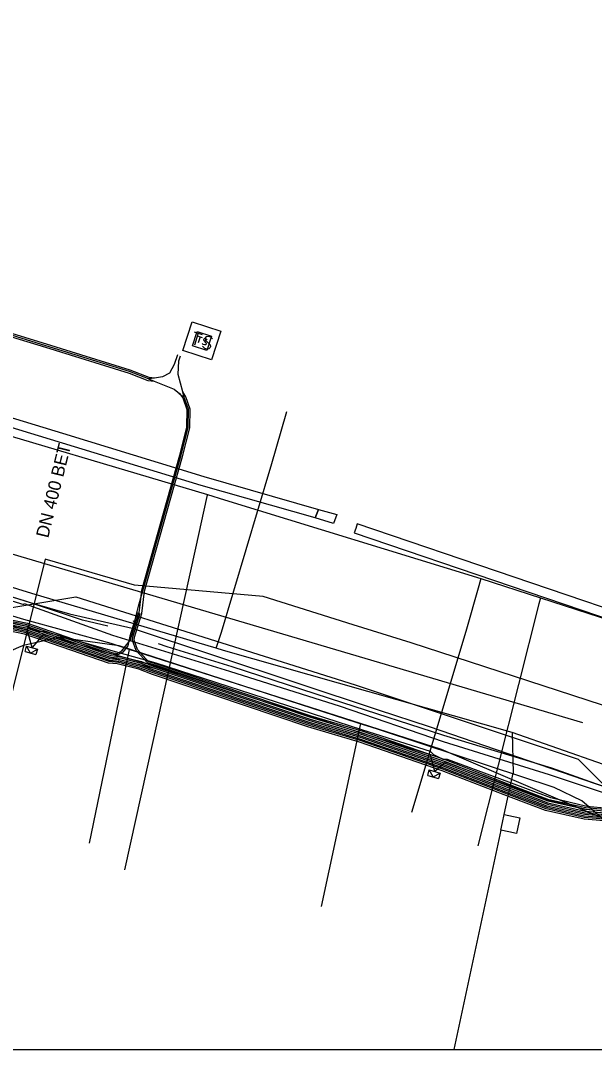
# Model space of a CAD drawing. Extents: x -599951 to -598963, y -1164095 to -1162939.
# Drawn here: x -599602.6 to -599566.7, y -1164094.7 to -1164030.3 of the extents above; entities that cross this region are included whole.
import ezdxf

# ---------------------------------------------------------------- set-up
doc = ezdxf.new("R2010")
doc.units = 0
for name, color, linetype in [('25', 7, 'Continuous'), ('31', 7, 'Continuous'), ('Level 3', 7, 'Continuous'), ('Vrstva 1', 7, 'Continuous'), ('Vrstva 12', 7, 'Continuous'), ('Vrstva 13', 7, 'Continuous'), ('Vrstva 16', 7, 'Continuous'), ('Vrstva 19', 7, 'Continuous'), ('Vrstva 3', 7, 'Continuous'), ('Vrstva 4', 7, 'Continuous'), ('Vrstva 42', 7, 'Continuous'), ('Vrstva 43', 7, 'Continuous'), ('Vrstva 44', 7, 'Continuous'), ('Vrstva 45', 7, 'Continuous'), ('Vrstva 53', 7, 'Continuous'), ('Vrstva 55', 7, 'Continuous'), ('Vrstva 58', 7, 'Continuous')]:
    doc.layers.add(name, color=color, linetype=linetype)

# ---------------------------------------------------------------- blocks, each defined once
blk = doc.blocks.new('VN640')
at = {"layer": '25'}
for points in [[(-1.89, 1.889), (1.889, 1.889)], [(-1.89, -1.89), (-1.89, 1.889)], [(-1.26, 0.787), (-0.221, 0.787)], [(-0.725, 0.787), (-0.725, -0.788)], [(1.197, 0.661), (0.945, 0.787), (0.661, 0.787), (0.409, 0.661), (0.283, 0.472), (0.283, 0.409), (0.409, 0.22), (1.133, -0.158), (1.259, -0.316), (1.259, -0.473), (1.133, -0.662), (0.913, -0.788), (0.629, -0.788), (0.503, -0.725), (0.283, -0.599)], [(1.889, 1.889), (1.889, -1.89)], [(1.889, -1.89), (-1.89, -1.89)]]:
    blk.add_lwpolyline(points, dxfattribs=at)
blk = doc.blocks.new('NN640')
at = {"layer": '25'}
for points in [[(-1.89, 1.889), (1.889, 1.889)], [(-1.89, -1.89), (-1.89, 1.889)], [(1.889, 1.889), (1.889, -1.89)], [(-1.26, 0.787), (-0.221, 0.787)], [(-0.725, 0.787), (-0.725, -0.788)], [(1.197, 0.661), (0.945, 0.787), (0.661, 0.787), (0.409, 0.661), (0.283, 0.472), (0.283, 0.409), (0.409, 0.22), (1.133, -0.158), (1.259, -0.316), (1.259, -0.473), (1.133, -0.662), (0.913, -0.788), (0.629, -0.788), (0.503, -0.725), (0.283, -0.599)], [(1.889, -1.89), (-1.89, -1.89)]]:
    blk.add_lwpolyline(points, dxfattribs=at)
blk = doc.blocks.new('NN630')
at = {"layer": '31'}
for points in [[(-0.003, -0.7), (-0.703, 0)], [(-0.703, -0.7), (-0.703, 0), (0.697, 0), (0.697, -0.7)], [(-0.003, -0.7), (0.697, 0)], [(-0.703, -0.7), (0.697, -0.7)]]:
    blk.add_lwpolyline(points, dxfattribs=at)

msp = doc.modelspace()

# ---------------------------------------------------------------- linework, layer by layer
at = {"layer": 'Level 3'}
msp.add_lwpolyline([(-599670.761, -1164034.874), (-599635.968, -1164045.241), (-599626.064, -1164047.883), (-599617.019, -1164050.914), (-599600, -1164056.104), (-599591.155, -1164058.802), (-599583.98, -1164060.87), (-599584.17, -1164061.41), (-599591.325, -1164059.378), (-599600, -1164056.732), (-599617.201, -1164051.486), (-599626.236, -1164048.457), (-599636.132, -1164045.819), (-599670.939, -1164035.446)], dxfattribs=at)
msp.add_lwpolyline([(-599584.17, -1164061.41), (-599583.98, -1164060.87), (-599582.83, -1164061.2), (-599583.03, -1164061.76)], close=True, dxfattribs=at)
at = {"layer": 'Vrstva 1'}
msp.add_line((-599567.415, -1164074.246), (-599604.11, -1164063.39), dxfattribs=at)
at = {"layer": 'Vrstva 12'}
msp.add_line((-599581.54, -1164074.23), (-599596.47, -1164069.41), dxfattribs=at)
for points in [[(-599613.46, -1164062.85), (-599613.16, -1164063.2), (-599611.72, -1164063.65), (-599602.03, -1164066.71), (-599599.57, -1164067.42), (-599595.65, -1164068.31), (-599580.24, -1164073.43), (-599577.04, -1164074.47), (-599566.64, -1164078.04), (-599562.59, -1164079.3), (-599551.43, -1164082.77), (-599546.18, -1164085.05), (-599534.35, -1164089.62), (-599520.153, -1164094.695)], [(-599512.817, -1164094.695), (-599549.011, -1164079.426), (-599551.753, -1164080.567), (-599560.66, -1164074.929), (-599578.175, -1164069.238), (-599581.79, -1164068.099), (-599587.439, -1164066.331), (-599595.493, -1164065.607), (-599599.144, -1164064.549), (-599601.105, -1164063.983), (-599607.16, -1164088.185), (-599608.496, -1164094.695)], [(-599596.47, -1164069.41), (-599600.24, -1164068.89), (-599602.46, -1164069.4), (-599602.72, -1164069.51), (-599603.14, -1164069.68), (-599603.87, -1164071.93)], [(-599565.95, -1164080.45), (-599567.47, -1164079.13), (-599569.21, -1164078.29), (-599577.43, -1164075.58), (-599580.28, -1164074.63), (-599581.54, -1164074.23)]]:
    msp.add_lwpolyline(points, dxfattribs=at)
at = {"layer": 'Vrstva 13'}
for points in [[(-599607.67, -1164054.96), (-599590.92, -1164059.94), (-599589.853, -1164060.27), (-599573.8, -1164065.2), (-599570.07, -1164066.42), (-599549.24, -1164073.15), (-599540.472, -1164075.88), (-599508.435, -1164089.969), (-599502.44, -1164092.61), (-599497.429, -1164094.695)], [(-599590.92, -1164059.94), (-599590.96, -1164060.07), (-599591.68, -1164063.31), (-599596.119, -1164083.448)], [(-599573.8, -1164065.2), (-599573.93, -1164065.66), (-599574.75, -1164068.52), (-599578.146, -1164079.846)], [(-599570.07, -1164066.42), (-599570.16, -1164066.78), (-599573.98, -1164081.94)]]:
    msp.add_lwpolyline(points, dxfattribs=at)
at = {"layer": 'Vrstva 16'}
for points in [[(-599532.23, -1164094.695), (-599576.26, -1164075.92), (-599581.33, -1164074.29), (-599595.84, -1164069.64), (-599596.96, -1164069.28), (-599602.44, -1164067.76), (-599618.73, -1164062.85), (-599666.38, -1164048.5), (-599672.28, -1164046.86), (-599687.99, -1164042.5)], [(-599595.84, -1164069.64), (-599598.33, -1164081.77)], [(-599581.33, -1164074.29), (-599583.8, -1164085.75)]]:
    msp.add_lwpolyline(points, dxfattribs=at)
at = {"layer": 'Vrstva 19'}
for points in [[(-599517.408, -1164094.695), (-599537.5, -1164086.87), (-599571.84, -1164074.84), (-599589.93, -1164069.71), (-599590.38, -1164069.57), (-599590.89, -1164069.41), (-599601.93, -1164066.13), (-599608.97, -1164063.96), (-599646.01, -1164052.54), (-599646.71, -1164052.33), (-599646.97, -1164052.25), (-599649.244, -1164051.504), (-599665.68, -1164046.42), (-599687.59, -1164039.86)], [(-599590.38, -1164069.57), (-599590.19, -1164068.99), (-599590.05, -1164068.56), (-599586.96, -1164058.21), (-599586.94, -1164058.14), (-599585.95, -1164054.74)], [(-599571.84, -1164074.84), (-599571.77, -1164077.39)], [(-599572.44, -1164080.48), (-599572.33, -1164079.99), (-599571.77, -1164077.39)], [(-599572.33, -1164079.99), (-599572.04, -1164080.05), (-599571.35, -1164080.2), (-599571.56, -1164081.18), (-599572.05, -1164081.07), (-599572.54, -1164080.97), (-599575.487, -1164094.695)], [(-599572.54, -1164080.97), (-599572.44, -1164080.48)]]:
    msp.add_lwpolyline(points, dxfattribs=at)
at = {"layer": 'Vrstva 3'}
msp.add_lwpolyline([(-599492.33, -1164094.695), (-599491.183, -1164094.695), (-599491.12, -1164094.53), (-599497.905, -1164092.099), (-599500, -1164091.28), (-599520.117, -1164083.412), (-599528.111, -1164080.071), (-599548.984, -1164072.466), (-599561.867, -1164068.455), (-599581.544, -1164061.776), (-599581.64, -1164062.06), (-599581.735, -1164062.342), (-599562.053, -1164069.025), (-599549.176, -1164073.034), (-599528.329, -1164080.629), (-599520.343, -1164083.968), (-599500, -1164091.924), (-599498.115, -1164092.661)], close=True, dxfattribs=at)
at = {"layer": 'Vrstva 42'}
for points in [[(-599565.43, -1164079.839), (-599567.196, -1164079.669), (-599569.479, -1164079.126), (-599572.125, -1164078.144), (-599576.007, -1164076.713), (-599576.69, -1164077.29), (-599576.872, -1164076.585), (-599576.961, -1164076.241), (-599581.25, -1164074.885), (-599584.411, -1164073.875), (-599594.199, -1164070.686), (-599597.037, -1164069.906), (-599601.23, -1164068.704), (-599601.92, -1164069.53), (-599602.229, -1164068.421), (-599611.444, -1164066.257), (-599613.443, -1164065.737), (-599616.851, -1164065.018), (-599617.63, -1164065.53)], [(-599565.41, -1164079.64), (-599567.164, -1164079.471), (-599569.421, -1164078.934), (-599572.055, -1164077.956), (-599575.885, -1164076.546), (-599576.152, -1164076.53), (-599576.753, -1164076.243), (-599576.96, -1164076.035), (-599581.19, -1164074.695), (-599584.349, -1164073.685), (-599594.141, -1164070.494), (-599596.983, -1164069.714), (-599601.132, -1164068.524), (-599601.444, -1164068.54), (-599601.897, -1164068.412), (-599602.237, -1164068.213), (-599611.396, -1164066.063)]]:
    msp.add_lwpolyline(points, dxfattribs=at)
at = {"layer": 'Vrstva 44'}
for p, q in [((-599601.05, -1164050.62), (-599606.97, -1164048.81)), ((-599595.81, -1164052.24), (-599601.05, -1164050.62)), ((-599594.62, -1164052.7), (-599595.81, -1164052.24)), ((-599594.247, -1164052.645), (-599594.62, -1164052.7)), ((-599594.62, -1164052.7), (-599594.274, -1164052.838)), ((-599592.38, -1164053.86), (-599592.473, -1164053.51)), ((-599592.717, -1164053.586), (-599592.38, -1164053.86)), ((-599592.11, -1164054.6), (-599592.38, -1164053.86)), ((-599592.14, -1164055.74), (-599592.11, -1164054.6)), ((-599592.59, -1164057.53), (-599592.14, -1164055.74)), ((-599595.24, -1164066.94), (-599592.59, -1164057.53)), ((-599595.48, -1164067.85), (-599595.24, -1164066.94)), ((-599595.48, -1164067.85), (-599595.594, -1164067.891)), ((-599595.432, -1164068.06), (-599595.48, -1164067.85))]:
    msp.add_line(p, q, dxfattribs=at)
for points in [[(-599592.804, -1164051.197), (-599593.016, -1164051.8), (-599593.3, -1164052.33), (-599593.74, -1164052.57), (-599594.247, -1164052.645), (-599594.584, -1164052.607), (-599595.777, -1164052.146), (-599601.021, -1164050.524), (-599606.942, -1164048.714), (-599614.66, -1164046.524), (-599624.688, -1164043.135), (-599633.419, -1164040.135), (-599640.341, -1164037.974), (-599642.239, -1164037.405), (-599644.228, -1164036.705), (-599647.942, -1164035.504), (-599650.972, -1164034.727), (-599651.601, -1164034.365), (-599651.846, -1164034.01), (-599652.008, -1164033.22), (-599651.724, -1164031.781)], [(-599713.076, -1164035.902), (-599703.955, -1164038.752), (-599695.016, -1164041.252), (-599688.692, -1164043.173), (-599677.704, -1164046.543), (-599672.728, -1164047.994), (-599667.14, -1164049.944), (-599657.488, -1164052.642), (-599649.966, -1164054.832), (-599642.274, -1164057.053), (-599633.284, -1164059.853), (-599627.565, -1164061.482), (-599619.491, -1164063.974), (-599613.646, -1164065.724), (-599612.857, -1164065.953), (-599611.723, -1164066.031), (-599602.21, -1164068), (-599596.912, -1164069.837), (-599596.588, -1164069.897), (-599596.29, -1164069.74), (-599595.75, -1164069.044), (-599595.695, -1164068.82), (-599595.236, -1164067.34)], [(-599606.998, -1164048.906), (-599601.079, -1164050.716), (-599595.843, -1164052.335), (-599594.656, -1164052.793), (-599594.274, -1164052.838), (-599593.02, -1164053.34), (-599592.676, -1164053.62), (-599592.474, -1164053.894), (-599592.21, -1164054.616), (-599592.24, -1164055.726), (-599592.687, -1164057.504), (-599595.064, -1164065.946), (-599595.236, -1164067.34)], [(-599595.044, -1164067.4), (-599594.871, -1164065.998), (-599592.493, -1164057.556), (-599592.04, -1164055.754), (-599592.01, -1164054.584), (-599592.286, -1164053.826), (-599592.473, -1164053.51), (-599592.76, -1164052.43), (-599592.724, -1164051.573), (-599592.616, -1164051.263)], [(-599657.543, -1164052.834), (-599650.022, -1164055.024), (-599642.331, -1164057.244), (-599633.341, -1164060.044), (-599627.622, -1164061.674), (-599619.551, -1164064.164), (-599613.642, -1164065.934), (-599612.892, -1164066.151), (-599611.736, -1164066.231), (-599602.263, -1164068.193), (-599596.981, -1164070.024), (-599596.262, -1164070.1), (-599595.065, -1164070.401), (-599594.222, -1164070.724), (-599584.49, -1164074.005), (-599581.239, -1164074.975), (-599576.046, -1164076.776), (-599572.154, -1164078.277), (-599569.601, -1164079.244), (-599567.255, -1164079.771), (-599563.761, -1164080.071)], [(-599657.597, -1164053.026), (-599650.078, -1164055.216), (-599642.389, -1164057.436), (-599633.399, -1164060.236), (-599627.678, -1164061.866), (-599619.609, -1164064.356), (-599613.698, -1164066.126), (-599612.928, -1164066.349), (-599611.764, -1164066.429), (-599602.317, -1164068.387), (-599597.039, -1164070.216), (-599596.349, -1164070.287), (-599595.132, -1164070.597), (-599594.278, -1164070.916), (-599584.55, -1164074.195), (-599581.301, -1164075.165), (-599576.114, -1164076.964), (-599572.226, -1164078.463), (-599569.659, -1164079.436), (-599567.285, -1164079.969), (-599563.799, -1164080.269)], [(-599618.59, -1164094.695), (-599618.44, -1164093.46), (-599617.57, -1164088.71), (-599616.32, -1164081.87), (-599615.21, -1164076.36), (-599614.51, -1164071.62), (-599613.41, -1164066.72), (-599612.86, -1164065.45), (-599612.32, -1164064.9), (-599611.41, -1164064.41), (-599610.74, -1164064.29), (-599602.44, -1164066.82), (-599602.41, -1164066.76), (-599596.88, -1164068.74), (-599589.54, -1164071.01), (-599582.61, -1164073.2), (-599576.16, -1164075.41), (-599569.51, -1164077.47), (-599564.88, -1164079.03)], [(-599597.17, -1164068.19), (-599598.76, -1164067.8), (-599602.39, -1164066.59), (-599610.72, -1164064.09)], [(-599612.91, -1164066.25), (-599611.75, -1164066.33), (-599602.29, -1164068.29), (-599597.01, -1164070.12), (-599594.25, -1164070.82)], [(-599563.837, -1164080.466), (-599567.316, -1164080.167), (-599569.716, -1164079.628), (-599572.297, -1164078.65), (-599576.183, -1164077.152), (-599581.362, -1164075.356), (-599584.611, -1164074.386), (-599594.335, -1164071.108), (-599595.198, -1164070.786), (-599596.483, -1164070.459), (-599597.096, -1164070.408), (-599602.37, -1164068.58), (-599611.745, -1164066.637), (-599612.583, -1164066.566), (-599613.275, -1164066.762), (-599613.683, -1164067.492), (-599614.101, -1164070.576), (-599615.223, -1164076.303), (-599615.651, -1164077.875), (-599616.131, -1164080.965), (-599616.302, -1164082.144), (-599616.846, -1164083.683)], [(-599548.889, -1164085.258), (-599551.295, -1164084.429), (-599552.972, -1164083.76), (-599561.884, -1164080.426), (-599563.723, -1164079.874), (-599567.224, -1164079.573), (-599569.544, -1164079.052), (-599572.083, -1164078.09), (-599575.977, -1164076.588), (-599581.178, -1164074.784), (-599584.429, -1164073.814), (-599594.158, -1164070.534), (-599594.617, -1164070.415), (-599595.31, -1164069.65), (-599595.524, -1164069.061), (-599595.504, -1164068.88), (-599595.044, -1164067.4)], [(-599520.995, -1164094.695), (-599522.17, -1164094.21), (-599525.69, -1164092.63), (-599532.76, -1164089.83), (-599539.63, -1164087.15), (-599546.86, -1164084.73), (-599552.99, -1164082.57), (-599562.25, -1164079.36), (-599564.77, -1164078.7), (-599569.35, -1164077.07), (-599576.12, -1164075.03), (-599582.45, -1164072.98), (-599589.38, -1164070.73), (-599593.46, -1164069.48), (-599593.99, -1164069.3)], [(-599594.25, -1164070.82), (-599584.52, -1164074.1), (-599581.27, -1164075.07), (-599576.08, -1164076.87), (-599572.19, -1164078.37), (-599569.63, -1164079.34), (-599567.27, -1164079.87), (-599563.78, -1164080.17), (-599561.98, -1164080.71), (-599553.08, -1164084.04), (-599551.4, -1164084.71), (-599548.99, -1164085.54)]]:
    msp.add_lwpolyline(points, dxfattribs=at)
at = {"layer": 'Vrstva 53'}
msp.add_lwpolyline([(-599951.125, -1164094.695), (-598963.215, -1164094.695), (-598963.215, -1162939.4), (-599951.125, -1162939.4)], close=True, dxfattribs=at)
at = {"layer": 'Vrstva 55'}
msp.add_lwpolyline([(-599730.225, -1164030.406), (-599699.561, -1164039.03), (-599699.101, -1164037.918), (-599699.561, -1164039.03), (-599667.715, -1164049.284), (-599667.086, -1164049.415), (-599666.671, -1164048.038), (-599667.086, -1164049.415), (-599641.77, -1164056.83), (-599641.359, -1164055.754), (-599641.77, -1164056.83), (-599613.23, -1164064.88), (-599603.95, -1164067.14), (-599599.17, -1164066.34), (-599581.67, -1164071.86), (-599567.7, -1164076.51), (-599564.49, -1164079.74), (-599552.92, -1164083.71), (-599548.31, -1164083.01), (-599521.3, -1164092.7), (-599516.137, -1164094.695)], dxfattribs=at)
at = {"layer": 'Vrstva 58'}
for points in [[(-599595.341, -1164067.328), (-599595.8, -1164068.805), (-599595.92, -1164069.426), (-599596.224, -1164069.818), (-599596.541, -1164069.986), (-599596.945, -1164069.931), (-599602.237, -1164068.097), (-599611.736, -1164066.13), (-599612.875, -1164066.052), (-599613.674, -1164065.82), (-599619.522, -1164064.069), (-599627.593, -1164061.578), (-599633.313, -1164059.948), (-599642.303, -1164057.148), (-599649.994, -1164054.928), (-599657.515, -1164052.738), (-599667.17, -1164050.039), (-599672.759, -1164048.089), (-599677.733, -1164046.638), (-599688.722, -1164043.269), (-599695.044, -1164041.348), (-599703.983, -1164038.848), (-599713.104, -1164035.998)], [(-599657.625, -1164053.122), (-599650.106, -1164055.312), (-599642.417, -1164057.532), (-599633.427, -1164060.332), (-599627.707, -1164061.962), (-599619.638, -1164064.451), (-599613.726, -1164066.222), (-599612.945, -1164066.448), (-599611.777, -1164066.529), (-599602.343, -1164068.483), (-599597.067, -1164070.312), (-599596.407, -1164070.375), (-599595.151, -1164070.695), (-599594.307, -1164071.012), (-599584.581, -1164074.291), (-599581.331, -1164075.26), (-599576.149, -1164077.058), (-599572.261, -1164078.557), (-599569.688, -1164079.532), (-599567.301, -1164080.068), (-599563.818, -1164080.367)], [(-599657.57, -1164052.93), (-599650.05, -1164055.12), (-599642.36, -1164057.34), (-599633.37, -1164060.14), (-599627.65, -1164061.77), (-599619.58, -1164064.26), (-599613.67, -1164066.03), (-599612.91, -1164066.25), (-599611.75, -1164066.33), (-599602.29, -1164068.29), (-599597.01, -1164070.12), (-599596.288, -1164070.199), (-599595.11, -1164070.499), (-599594.25, -1164070.82), (-599584.52, -1164074.1), (-599581.27, -1164075.07), (-599576.08, -1164076.87), (-599572.19, -1164078.37), (-599569.63, -1164079.34), (-599567.27, -1164079.87), (-599563.78, -1164080.17)], [(-599563.855, -1164080.565), (-599567.331, -1164080.266), (-599569.745, -1164079.724), (-599572.333, -1164078.744), (-599576.218, -1164077.246), (-599581.393, -1164075.451), (-599584.641, -1164074.481), (-599594.363, -1164071.204), (-599595.228, -1164070.882), (-599596.591, -1164070.535), (-599597.125, -1164070.504), (-599602.397, -1164068.676), (-599611.759, -1164066.737), (-599612.591, -1164066.665), (-599613.188, -1164066.811), (-599613.587, -1164067.525), (-599614.003, -1164070.593)], [(-599563.742, -1164079.972), (-599567.239, -1164079.672), (-599569.572, -1164079.148), (-599572.119, -1164078.183), (-599576.011, -1164076.682), (-599581.209, -1164074.88), (-599584.459, -1164073.909), (-599594.186, -1164070.63), (-599594.671, -1164070.505), (-599595.397, -1164069.703), (-599595.626, -1164069.073), (-599595.603, -1164068.859), (-599595.14, -1164067.37)]]:
    msp.add_lwpolyline(points, dxfattribs=at)

# ---------------------------------------------------------------- block references
at = {"layer": 'Vrstva 43', "yscale": 0.5000000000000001}
for name, p, xscale, rotation in [('NN640', (-599591.277, -1164050.316), 0.49999999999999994, -18.000000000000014), ('NN630', (-599601.92, -1164069.53), 0.5, -16.000000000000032), ('NN630', (-599576.69, -1164077.29), 0.5, -16.000000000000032)]:
    msp.add_blockref(name, p, dxfattribs=dict(at, xscale=xscale, rotation=rotation))
at = {"layer": 'Vrstva 45', "xscale": 0.24999999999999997, "yscale": 0.25000000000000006, "rotation": -18.000000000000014}
msp.add_blockref('VN640', (-599591.277, -1164050.316), dxfattribs=at)

# ---------------------------------------------------------------- texts
at = {"layer": 'Vrstva 4'}
msp.add_text('DN 400 BET', height=0.8, rotation=76.14365, dxfattribs=at).set_placement((-599600.909, -1164062.705))

doc.saveas('drawing.dxf')
